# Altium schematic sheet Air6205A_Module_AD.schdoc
size 127 x 99 mm
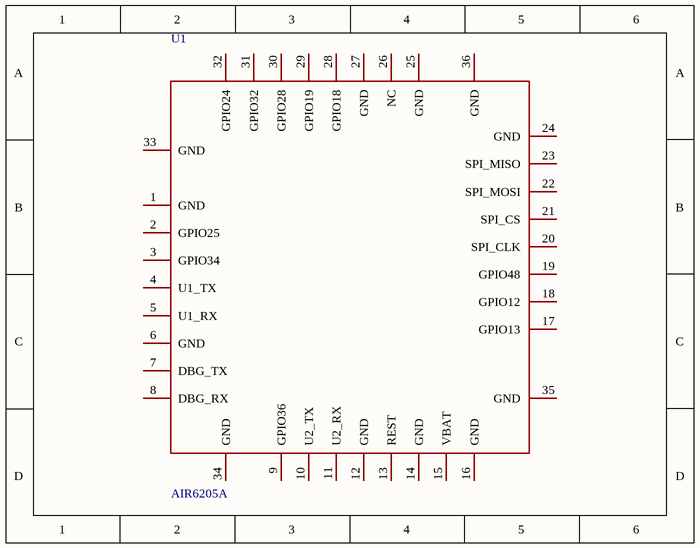
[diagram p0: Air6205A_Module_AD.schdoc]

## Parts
U1  AIR6205A  [AIR6205A-MODULE-PADS]

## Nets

Not connected (* = marked no-connect by the designer): U1 1(GND) 2(GPIO25) 3(GPIO34) 4(U1_TX) 5(U1_RX) 6(GND) 7(DBG_TX) 8(DBG_RX) 9(GPIO36) 10(U2_TX) 11(U2_RX) 12(GND) 13(REST) 14(GND) 15(VBAT) 16(GND) 17(GPIO13) 18(GPIO12) 19(GPIO48) 20(SPI_CLK) 21(SPI_CS) 22(SPI_MOSI) 23(SPI_MISO) 24(GND) 25(GND) 26(NC) 27(GND) 28(GPIO18) 29(GPIO19) 30(GPIO28) 31(GPIO32) 32(GPIO24) 33(GND) 34(GND) 35(GND) 36(GND)

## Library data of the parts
U1 = AIR6205A: Add into BOM: yes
